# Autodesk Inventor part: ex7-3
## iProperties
Shininess: 64.0
Length Units: 11272
Angle Units: 11279
Time Units: 11290
Mass Units: 11286
Length Display Precision: 3
Angle Display Precision: 2
Compacted: True
Part Number: ex7-3
Document SubType Name: Modeling
Created: 2002-11
Designer: Elise Moss
Density: 0.0
Volumn: 0.0
Area: 0.0
PropertySet Name: Model Information
Control State: 0
Master: False
Checked Out: False
Author: Elise Moss
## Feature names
1. Hole1
2. Hole2
3. Base1
